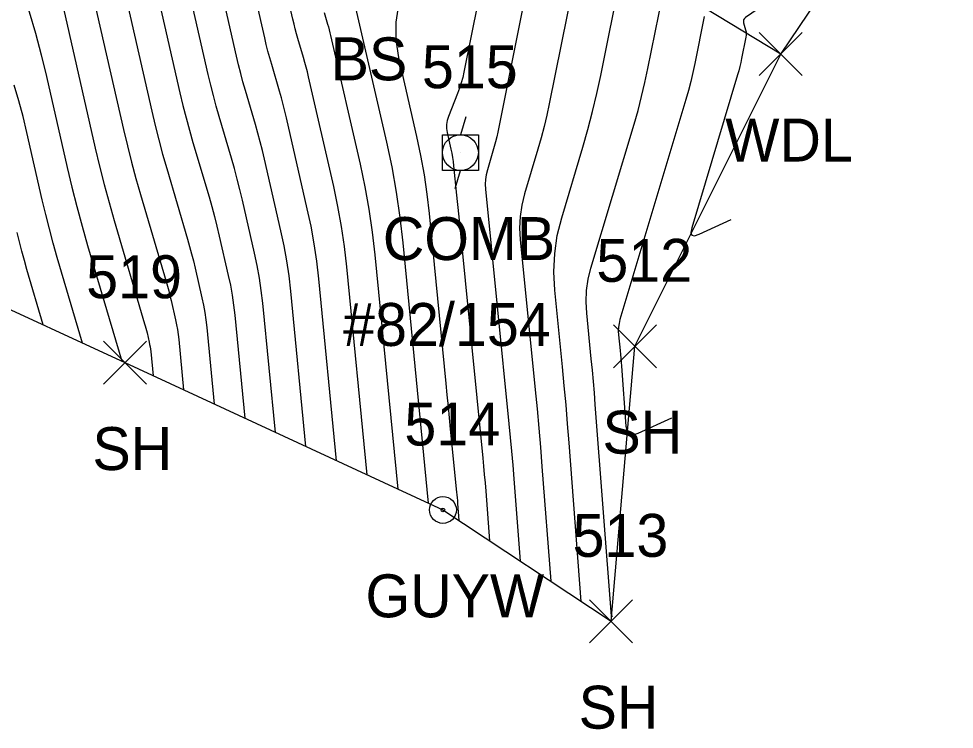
# Model space of a CAD drawing. Extents: x 1650836 to 1652450, y 332578 to 333908.
# Drawn here: x 1652341.6 to 1652385.16, y 332578.03 to 332611.11 of the extents above; entities that cross this region are included whole.
import ezdxf

# ---------------------------------------------------------------- set-up
doc = ezdxf.new("R2010")
doc.units = 0
for name, color, linetype in [('L_A', 7, 'Continuous'), ('L_I', 7, 'Continuous'), ('L_TIC', 7, 'Continuous'), ('LAWA', 7, 'Continuous'), ('LSOGCMA', 7, 'Continuous'), ('LSOGCMI', 7, 'Continuous'), ('LSOGP', 7, 'Continuous'), ('U_A', 7, 'Continuous'), ('U_C', 7, 'Continuous'), ('U_I', 7, 'Continuous'), ('UP', 7, 'Continuous'), ('UPGW', 7, 'Continuous')]:
    doc.layers.add(name, color=color, linetype=linetype)

msp = doc.modelspace()

# ---------------------------------------------------------------- linework, layer by layer
at = {"layer": 'L_TIC'}
for points in [[(1652376.083, 332608.462), (1652378.083, 332610.462)], [(1652378.083, 332608.462), (1652376.083, 332610.462)], [(1652369.294, 332594.861), (1652371.294, 332596.861)], [(1652371.294, 332594.861), (1652369.294, 332596.861)], [(1652345.545, 332594.098), (1652347.545, 332596.098)], [(1652347.545, 332594.098), (1652345.545, 332596.098)], [(1652368.183, 332582.057), (1652370.183, 332584.057)], [(1652370.183, 332582.057), (1652368.183, 332584.057)]]:
    msp.add_lwpolyline(points, dxfattribs=at)
at = {"layer": 'LAWA'}
msp.add_lwpolyline([(1652377.083, 332609.462), (1652362.423, 332618.359), (1652352.896, 332629.018), (1652326.723, 332645.943), (1652287.129, 332663.549), (1652263.425, 332671.343), (1652249.055, 332682.968), (1652227.219, 332684.809), (1652198.28, 332683.973), (1652188.25, 332681.448)], dxfattribs=at)
at = {"layer": 'LSOGCMA'}
for points in [[(1652344.97, 332619.203), (1652347.797, 332606.803), (1652347.955, 332606.133), (1652348.124, 332605.465), (1652348.303, 332604.8), (1652348.493, 332604.138), (1652349.463, 332600.846), (1652349.56, 332600.509), (1652349.651, 332600.171), (1652349.737, 332599.831), (1652349.818, 332599.49), (1652350.131, 332598.123), (1652350.204, 332597.781), (1652350.265, 332597.436), (1652350.316, 332597.09), (1652350.356, 332596.742), (1652350.705, 332593.172)], [(1652365.779, 332615.161), (1652363.905, 332605.829), (1652363.858, 332605.606), (1652363.805, 332605.384), (1652363.747, 332605.163), (1652363.684, 332604.944), (1652363.422, 332604.069), (1652363.368, 332603.849), (1652363.336, 332603.627), (1652363.325, 332603.403), (1652363.337, 332603.177), (1652364.429, 332592.245), (1652364.491, 332591.607), (1652364.549, 332590.97), (1652364.603, 332590.332), (1652364.654, 332589.693), (1652364.946, 332585.862)]]:
    msp.add_lwpolyline(points, dxfattribs=at)
at = {"layer": 'LSOGCMI'}
for points in [[(1652345.611, 332623.011), (1652349.111, 332607.659), (1652349.249, 332607.078), (1652349.395, 332606.499), (1652349.55, 332605.922), (1652349.715, 332605.348), (1652350.462, 332602.813), (1652350.591, 332602.361), (1652350.714, 332601.907), (1652350.829, 332601.451), (1652350.938, 332600.993), (1652351.358, 332599.159), (1652351.456, 332598.699), (1652351.539, 332598.237), (1652351.607, 332597.772), (1652351.66, 332597.305), (1652352.129, 332592.512)], [(1652353.553, 332591.853), (1652352.964, 332597.868), (1652352.897, 332598.454), (1652352.812, 332599.037), (1652352.708, 332599.617), (1652352.586, 332600.194), (1652352.02, 332602.662), (1652351.904, 332603.154), (1652351.78, 332603.644), (1652351.648, 332604.132), (1652351.509, 332604.618), (1652350.937, 332606.558), (1652350.797, 332607.045), (1652350.666, 332607.533), (1652350.542, 332608.023), (1652350.426, 332608.515), (1652347.801, 332620.027)], [(1652341.176, 332619.583), (1652342.556, 332615.56), (1652342.878, 332614.578), (1652343.174, 332613.588), (1652343.444, 332612.591), (1652343.687, 332611.586), (1652345.168, 332605.091), (1652345.368, 332604.243), (1652345.582, 332603.398), (1652345.809, 332602.556), (1652346.049, 332601.718), (1652347.465, 332596.911), (1652347.496, 332596.805), (1652347.525, 332596.698), (1652347.552, 332596.591), (1652347.577, 332596.484), (1652347.676, 332596.052), (1652347.699, 332595.944), (1652347.719, 332595.836), (1652347.735, 332595.726), (1652347.747, 332595.617), (1652347.857, 332594.49)], [(1652339.716, 332618.381), (1652341.762, 332612.416), (1652342.086, 332611.43), (1652342.383, 332610.437), (1652342.653, 332609.436), (1652342.897, 332608.428), (1652343.865, 332604.184), (1652344.081, 332603.272), (1652344.31, 332602.364), (1652344.554, 332601.459), (1652344.812, 332600.558), (1652346.402, 332595.164)], [(1652354.977, 332591.193), (1652354.269, 332598.43), (1652354.188, 332599.136), (1652354.085, 332599.837), (1652353.96, 332600.535), (1652353.813, 332601.229), (1652353.046, 332604.577), (1652352.951, 332604.98), (1652352.849, 332605.381), (1652352.741, 332605.781), (1652352.627, 332606.179), (1652352.159, 332607.768), (1652352.045, 332608.167), (1652351.937, 332608.566), (1652351.835, 332608.968), (1652351.74, 332609.371), (1652349.686, 332618.379)], [(1652356.401, 332590.534), (1652355.573, 332598.993), (1652355.479, 332599.817), (1652355.359, 332600.637), (1652355.213, 332601.453), (1652355.04, 332602.265), (1652354.072, 332606.493), (1652353.998, 332606.807), (1652353.918, 332607.119), (1652353.834, 332607.431), (1652353.745, 332607.741), (1652353.381, 332608.979), (1652353.292, 332609.289), (1652353.208, 332609.6), (1652353.129, 332609.913), (1652353.055, 332610.227), (1652351.455, 332617.244)], [(1652363.988, 332616.867), (1652362.333, 332608.623), (1652362.276, 332608.371), (1652362.208, 332608.123), (1652362.129, 332607.878), (1652362.039, 332607.636), (1652361.61, 332606.563), (1652361.551, 332606.378), (1652361.521, 332606.191), (1652361.521, 332606.002), (1652361.551, 332605.81), (1652361.728, 332605.039), (1652361.769, 332604.846), (1652361.803, 332604.652), (1652361.832, 332604.456), (1652361.854, 332604.26), (1652361.987, 332602.901), (1652362.016, 332602.608), (1652362.045, 332602.316), (1652362.074, 332602.024), (1652362.103, 332601.732), (1652363.21, 332590.657), (1652363.247, 332590.272), (1652363.282, 332589.887), (1652363.315, 332589.502), (1652363.345, 332589.117), (1652363.522, 332586.805)], [(1652357.825, 332589.875), (1652356.877, 332599.556), (1652356.77, 332600.499), (1652356.632, 332601.438), (1652356.465, 332602.371), (1652356.268, 332603.3), (1652355.098, 332608.408), (1652355.044, 332608.633), (1652354.988, 332608.857), (1652354.927, 332609.08), (1652354.864, 332609.302), (1652354.603, 332610.189), (1652354.539, 332610.411), (1652354.479, 332610.634), (1652354.422, 332610.858), (1652354.369, 332611.083), (1652353.223, 332616.108)], [(1652344.328, 332615.395), (1652346.482, 332605.947), (1652346.662, 332605.188), (1652346.853, 332604.431), (1652347.056, 332603.678), (1652347.271, 332602.928), (1652348.464, 332598.879), (1652348.528, 332598.657), (1652348.588, 332598.435), (1652348.644, 332598.211), (1652348.698, 332597.987), (1652348.903, 332597.088), (1652348.951, 332596.863), (1652348.992, 332596.636), (1652349.025, 332596.408), (1652349.051, 332596.179), (1652349.281, 332593.831)], [(1652380.635, 332614.741), (1652375.448, 332611.175), (1652375.39, 332611.123), (1652375.355, 332611.062), (1652375.343, 332610.993), (1652375.355, 332610.915), (1652375.45, 332610.588), (1652375.468, 332610.506), (1652375.477, 332610.424), (1652375.475, 332610.341), (1652375.463, 332610.258), (1652375.264, 332609.265), (1652375.223, 332609.073), (1652375.177, 332608.881), (1652375.128, 332608.691), (1652375.073, 332608.501), (1652372.94, 332601.373), (1652372.902, 332601.157), (1652372.946, 332601.035), (1652373.073, 332601.008), (1652373.281, 332601.076), (1652374.78, 332601.765)], [(1652367.695, 332614.075), (1652366.304, 332607.148), (1652366.191, 332606.616), (1652366.065, 332606.087), (1652365.927, 332605.561), (1652365.777, 332605.038), (1652365.154, 332602.954), (1652365.024, 332602.43), (1652364.947, 332601.901), (1652364.922, 332601.367), (1652364.95, 332600.828), (1652365.649, 332593.833), (1652365.735, 332592.943), (1652365.816, 332592.052), (1652365.892, 332591.161), (1652365.963, 332590.269), (1652366.371, 332584.918)], [(1652367.796, 332583.975), (1652367.232, 332591.368), (1652367.161, 332592.252), (1652367.086, 332593.135), (1652367.006, 332594.017), (1652366.92, 332594.9), (1652366.563, 332598.48), (1652366.519, 332599.332), (1652366.558, 332600.175), (1652366.68, 332601.011), (1652366.885, 332601.839), (1652367.871, 332605.133), (1652368.108, 332605.959), (1652368.325, 332606.79), (1652368.523, 332607.626), (1652368.702, 332608.466), (1652369.637, 332613.12)], [(1652357.149, 332612.239), (1652358.722, 332605.371), (1652358.969, 332604.208), (1652359.179, 332603.038), (1652359.351, 332601.863), (1652359.486, 332600.681), (1652360.673, 332588.556)], [(1652369.256, 332583.302), (1652369.215, 332583.283), (1652369.209, 332583.281), (1652369.205, 332583.282), (1652369.202, 332583.286), (1652369.201, 332583.292), (1652368.448, 332593.153), (1652368.406, 332593.686), (1652368.36, 332594.218), (1652368.312, 332594.75), (1652368.26, 332595.282), (1652368.048, 332597.408), (1652368.021, 332597.937), (1652368.045, 332598.462), (1652368.121, 332598.981), (1652368.248, 332599.495), (1652370.254, 332606.197), (1652370.438, 332606.84), (1652370.608, 332607.487), (1652370.762, 332608.138), (1652370.902, 332608.793), (1652371.579, 332612.166)], [(1652359.284, 332611.754), (1652359.158, 332610.95), (1652359.158, 332610.135), (1652359.285, 332609.311), (1652360.127, 332605.631), (1652360.317, 332604.739), (1652360.477, 332603.843), (1652360.609, 332602.941), (1652360.713, 332602.035), (1652361.487, 332594.129), (1652361.539, 332593.597), (1652361.591, 332593.064), (1652361.644, 332592.532), (1652361.697, 332591.999), (1652361.99, 332589.069), (1652362.003, 332588.937), (1652362.015, 332588.805), (1652362.026, 332588.673), (1652362.037, 332588.541), (1652362.097, 332587.749)], [(1652355.824, 332611.399), (1652355.982, 332610.864), (1652356.021, 332610.729), (1652356.057, 332610.595), (1652356.091, 332610.46), (1652356.123, 332610.324), (1652357.495, 332604.336), (1652357.717, 332603.29), (1652357.906, 332602.238), (1652358.06, 332601.181), (1652358.182, 332600.118), (1652359.249, 332589.215)], [(1652373.521, 332611.212), (1652373.083, 332609.029), (1652372.993, 332608.606), (1652372.893, 332608.184), (1652372.783, 332607.765), (1652372.664, 332607.349), (1652369.596, 332597.101), (1652369.553, 332596.925), (1652369.527, 332596.748), (1652369.519, 332596.569), (1652369.528, 332596.389), (1652369.6, 332595.664), (1652369.618, 332595.482), (1652369.635, 332595.301), (1652369.65, 332595.119), (1652369.664, 332594.938), (1652369.878, 332592.145), (1652369.93, 332591.908), (1652370.042, 332591.773), (1652370.214, 332591.741), (1652370.446, 332591.81), (1652372.018, 332592.533)], [(1652344.574, 332596.01), (1652343.399, 332599.994), (1652343.209, 332600.659), (1652343.029, 332601.327), (1652342.859, 332601.998), (1652342.7, 332602.672), (1652341.986, 332605.806), (1652341.805, 332606.551), (1652341.606, 332607.29), (1652341.386, 332608.024)], [(1652342.746, 332596.856), (1652341.987, 332599.429), (1652341.864, 332599.859), (1652341.748, 332600.291), (1652341.638, 332600.724), (1652341.535, 332601.159)]]:
    msp.add_lwpolyline(points, dxfattribs=at)
at = {"layer": 'LSOGP'}
msp.add_lwpolyline([(1652279.734, 332615.362), (1652315.79, 332612.523), (1652339.409, 332598.399), (1652346.545, 332595.098), (1652361.354, 332588.241), (1652369.183, 332583.057), (1652370.294, 332595.861), (1652377.083, 332609.462), (1652382.141, 332616.979), (1652386.916, 332625.064), (1652388.914, 332629.021), (1652395.364, 332640.33), (1652402.111, 332652.828), (1652402.772, 332654.006), (1652404.073, 332656.539), (1652408.76, 332665.713), (1652415.318, 332676.268), (1652424.287, 332693.179), (1652433.14, 332710.163), (1652407.488, 332714.435), (1652390.75, 332724.392), (1652340.004, 332757.28), (1652322.392, 332778.396), (1652286.244, 332816.269)], dxfattribs=at)
at = {"layer": 'UP'}
for p, q in [((1652362.42, 332606.542), (1652362.17, 332605.709)), ((1652361.337, 332604.042), (1652361.337, 332605.709)), ((1652361.337, 332605.709), (1652363.003, 332605.709)), ((1652363.003, 332605.709), (1652363.003, 332604.042)), ((1652362.17, 332604.875), (1652362.17, 332604.875)), ((1652363.003, 332604.042), (1652361.337, 332604.042)), ((1652361.92, 332603.209), (1652362.17, 332604.042))]:
    msp.add_line(p, q, dxfattribs=at)
msp.add_circle((1652362.17, 332604.875), 0.833, dxfattribs=at)
at = {"layer": 'UPGW'}
for radius in [0.625, 0.0833]:
    msp.add_circle((1652361.354, 332588.241), radius, dxfattribs=at)

# ---------------------------------------------------------------- texts
at = {"layer": 'L_A'}
for s, p in [('BS', (1652356.127, 332608.243)), ('WDL', (1652374.5, 332604.462)), ('SH', (1652368.782, 332590.861)), ('SH', (1652345.033, 332590.098)), ('SH', (1652367.671, 332578.057))]:
    msp.add_text(s, height=2, dxfattribs=at).set_placement(p)
at = {"layer": 'L_I'}
for s, p in [('512', (1652368.499, 332598.861)), ('519', (1652344.742, 332598.098)), ('513', (1652367.388, 332586.057))]:
    msp.add_text(s, height=2, dxfattribs=at).set_placement(p)
at = {"layer": 'U_A'}
for s, p in [('COMB', (1652358.556, 332599.875)), ('GUYW', (1652357.748, 332583.241))]:
    msp.add_text(s, height=2, dxfattribs=at).set_placement(p)
at = {"layer": 'U_C'}
msp.add_text('#82/154', height=2, dxfattribs=at).set_placement((1652356.706, 332595.875))
at = {"layer": 'U_I'}
for s, p in [('515', (1652360.375, 332607.875)), ('514', (1652359.559, 332591.241))]:
    msp.add_text(s, height=2, dxfattribs=at).set_placement(p)

doc.saveas('drawing.dxf')
